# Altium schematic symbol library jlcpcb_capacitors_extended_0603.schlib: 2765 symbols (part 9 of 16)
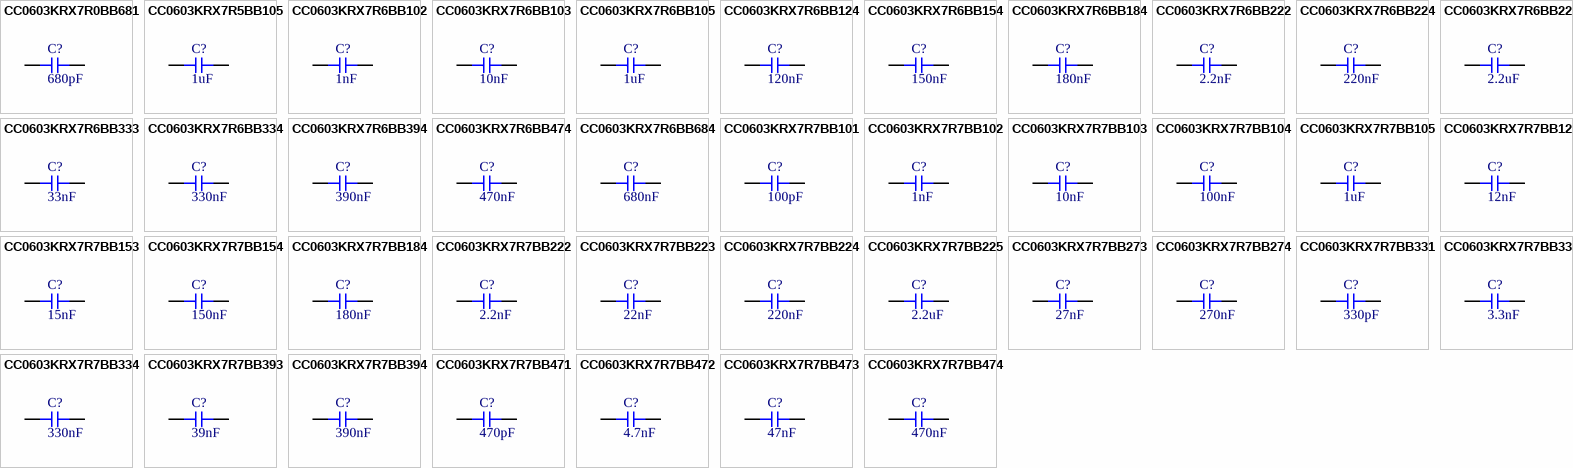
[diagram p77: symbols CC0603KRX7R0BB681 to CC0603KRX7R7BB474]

## CC0603KRX7R7BB334
designator C?  Capacitance: 330nF  (hidden comment: *)
Capacitor, Ceramic (MLCC), 330nF, ±10%, 16V, X7R, ±10%, SMD 0603; Manufacturer: YAGEO; Manufacturer Part Number: CC0603KRX7R7BB334
footprint CAP-0603 (0603 (1608M) Capacitor)
pins: 1, 2

## CC0603KRX7R7BB393
designator C?  Capacitance: 39nF  (hidden comment: *)
Capacitor, Ceramic (MLCC), 39nF, ±10%, 16V, X7R, ±10%, SMD 0603; Manufacturer: YAGEO; Manufacturer Part Number: CC0603KRX7R7BB393
footprint CAP-0603 (0603 (1608M) Capacitor)
pins: 1, 2

## CC0603KRX7R7BB394
designator C?  Capacitance: 390nF  (hidden comment: *)
Capacitor, Ceramic (MLCC), 390nF, ±10%, 16V, X7R, ±10%, SMD 0603; Manufacturer: YAGEO; Manufacturer Part Number: CC0603KRX7R7BB394
footprint CAP-0603 (0603 (1608M) Capacitor)
pins: 1, 2

## CC0603KRX7R7BB471
designator C?  Capacitance: 470pF  (hidden comment: *)
Capacitor, Ceramic (MLCC), 470pF, ±10%, 16V, X7R, ±10%, SMD 0603; Manufacturer: YAGEO; Manufacturer Part Number: CC0603KRX7R7BB471
footprint CAP-0603 (0603 (1608M) Capacitor)
pins: 1, 2

## CC0603KRX7R7BB472
designator C?  Capacitance: 4.7nF  (hidden comment: *)
Capacitor, Ceramic (MLCC), 4.7nF, ±10%, 16V, X7R, ±10%, SMD 0603; Manufacturer: YAGEO; Manufacturer Part Number: CC0603KRX7R7BB472
footprint CAP-0603 (0603 (1608M) Capacitor)
pins: 1, 2

## CC0603KRX7R7BB473
designator C?  Capacitance: 47nF  (hidden comment: *)
Capacitor, Ceramic (MLCC), 47nF, ±10%, 16V, X7R, ±10%, SMD 0603; Manufacturer: YAGEO; Manufacturer Part Number: CC0603KRX7R7BB473
footprint CAP-0603 (0603 (1608M) Capacitor)
pins: 1, 2

## CC0603KRX7R7BB474
designator C?  Capacitance: 470nF  (hidden comment: *)
Capacitor, Ceramic (MLCC), 470nF, ±10%, 16V, X7R, ±10%, SMD 0603; Manufacturer: YAGEO; Manufacturer Part Number: CC0603KRX7R7BB474
footprint CAP-0603 (0603 (1608M) Capacitor)
pins: 1, 2

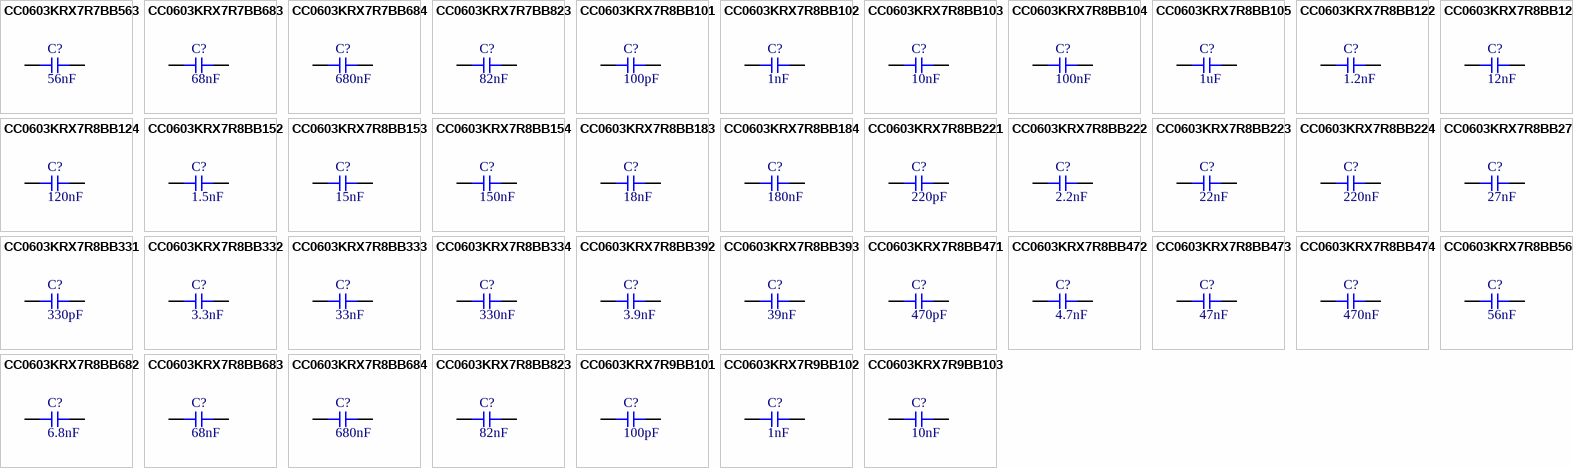
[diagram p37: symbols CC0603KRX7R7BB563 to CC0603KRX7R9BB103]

## CC0603KRX7R7BB563
designator C?  Capacitance: 56nF  (hidden comment: *)
Capacitor, Ceramic (MLCC), 56nF, ±10%, 16V, X7R, ±10%, SMD 0603; Manufacturer: YAGEO; Manufacturer Part Number: CC0603KRX7R7BB563
footprint CAP-0603 (0603 (1608M) Capacitor)
pins: 1, 2

## CC0603KRX7R7BB683
designator C?  Capacitance: 68nF  (hidden comment: *)
Capacitor, Ceramic (MLCC), 68nF, ±10%, 16V, X7R, ±10%, SMD 0603; Manufacturer: YAGEO; Manufacturer Part Number: CC0603KRX7R7BB683
footprint CAP-0603 (0603 (1608M) Capacitor)
pins: 1, 2

## CC0603KRX7R7BB684
designator C?  Capacitance: 680nF  (hidden comment: *)
Capacitor, Ceramic (MLCC), 680nF, ±10%, 16V, X7R, ±10%, SMD 0603; Manufacturer: YAGEO; Manufacturer Part Number: CC0603KRX7R7BB684
footprint CAP-0603 (0603 (1608M) Capacitor)
pins: 1, 2

## CC0603KRX7R7BB823
designator C?  Capacitance: 82nF  (hidden comment: *)
Capacitor, Ceramic (MLCC), 82nF, ±10%, 16V, X7R, ±10%, SMD 0603; Manufacturer: YAGEO; Manufacturer Part Number: CC0603KRX7R7BB823
footprint CAP-0603 (0603 (1608M) Capacitor)
pins: 1, 2

## CC0603KRX7R8BB101
designator C?  Capacitance: 100pF  (hidden comment: *)
Capacitor, Ceramic (MLCC), 100pF, ±10%, 25V, X7R, ±10%, SMD 0603; Manufacturer: YAGEO; Manufacturer Part Number: CC0603KRX7R8BB101
footprint CAP-0603 (0603 (1608M) Capacitor)
pins: 1, 2

## CC0603KRX7R8BB102
designator C?  Capacitance: 1nF  (hidden comment: *)
Capacitor, Ceramic (MLCC), 1nF, ±10%, 25V, X7R, ±10%, SMD 0603; Manufacturer: YAGEO; Manufacturer Part Number: CC0603KRX7R8BB102
footprint CAP-0603 (0603 (1608M) Capacitor)
pins: 1, 2

## CC0603KRX7R8BB103
designator C?  Capacitance: 10nF  (hidden comment: *)
Capacitor, Ceramic (MLCC), 10nF, ±10%, 25V, X7R, ±10%, SMD 0603; Manufacturer: YAGEO; Manufacturer Part Number: CC0603KRX7R8BB103
footprint CAP-0603 (0603 (1608M) Capacitor)
pins: 1, 2

## CC0603KRX7R8BB104
designator C?  Capacitance: 100nF  (hidden comment: *)
Capacitor, Ceramic (MLCC), 100nF, ±10%, 25V, X7R, ±10%, SMD 0603; Manufacturer: YAGEO; Manufacturer Part Number: CC0603KRX7R8BB104
footprint CAP-0603 (0603 (1608M) Capacitor)
pins: 1, 2

## CC0603KRX7R8BB105
designator C?  Capacitance: 1uF  (hidden comment: *)
Capacitor, Ceramic (MLCC), 1uF, ±10%, 25V, X7R, ±10%, SMD 0603; Manufacturer: YAGEO; Manufacturer Part Number: CC0603KRX7R8BB105
footprint CAP-0603 (0603 (1608M) Capacitor)
pins: 1, 2

## CC0603KRX7R8BB122
designator C?  Capacitance: 1.2nF  (hidden comment: *)
Capacitor, Ceramic (MLCC), 1.2nF, ±10%, 25V, X7R, ±10%, SMD 0603; Manufacturer: YAGEO; Manufacturer Part Number: CC0603KRX7R8BB122
footprint CAP-0603 (0603 (1608M) Capacitor)
pins: 1, 2

## CC0603KRX7R8BB123
designator C?  Capacitance: 12nF  (hidden comment: *)
Capacitor, Ceramic (MLCC), 12nF, ±10%, 25V, X7R, ±10%, SMD 0603; Manufacturer: YAGEO; Manufacturer Part Number: CC0603KRX7R8BB123
footprint CAP-0603 (0603 (1608M) Capacitor)
pins: 1, 2

## CC0603KRX7R8BB124
designator C?  Capacitance: 120nF  (hidden comment: *)
Capacitor, Ceramic (MLCC), 120nF, ±10%, 25V, X7R, ±10%, SMD 0603; Manufacturer: YAGEO; Manufacturer Part Number: CC0603KRX7R8BB124
footprint CAP-0603 (0603 (1608M) Capacitor)
pins: 1, 2

## CC0603KRX7R8BB152
designator C?  Capacitance: 1.5nF  (hidden comment: *)
Capacitor, Ceramic (MLCC), 1.5nF, ±10%, 25V, X7R, ±10%, SMD 0603; Manufacturer: YAGEO; Manufacturer Part Number: CC0603KRX7R8BB152
footprint CAP-0603 (0603 (1608M) Capacitor)
pins: 1, 2

## CC0603KRX7R8BB153
designator C?  Capacitance: 15nF  (hidden comment: *)
Capacitor, Ceramic (MLCC), 15nF, ±10%, 25V, X7R, ±10%, SMD 0603; Manufacturer: YAGEO; Manufacturer Part Number: CC0603KRX7R8BB153
footprint CAP-0603 (0603 (1608M) Capacitor)
pins: 1, 2

## CC0603KRX7R8BB154
designator C?  Capacitance: 150nF  (hidden comment: *)
Capacitor, Ceramic (MLCC), 150nF, ±10%, 25V, X7R, ±10%, SMD 0603; Manufacturer: YAGEO; Manufacturer Part Number: CC0603KRX7R8BB154
footprint CAP-0603 (0603 (1608M) Capacitor)
pins: 1, 2

## CC0603KRX7R8BB183
designator C?  Capacitance: 18nF  (hidden comment: *)
Capacitor, Ceramic (MLCC), 18nF, ±10%, 25V, X7R, ±10%, SMD 0603; Manufacturer: YAGEO; Manufacturer Part Number: CC0603KRX7R8BB183
footprint CAP-0603 (0603 (1608M) Capacitor)
pins: 1, 2

## CC0603KRX7R8BB184
designator C?  Capacitance: 180nF  (hidden comment: *)
Capacitor, Ceramic (MLCC), 180nF, ±10%, 25V, X7R, ±10%, SMD 0603; Manufacturer: YAGEO; Manufacturer Part Number: CC0603KRX7R8BB184
footprint CAP-0603 (0603 (1608M) Capacitor)
pins: 1, 2

## CC0603KRX7R8BB221
designator C?  Capacitance: 220pF  (hidden comment: *)
Capacitor, Ceramic (MLCC), 220pF, ±10%, 25V, X7R, ±10%, SMD 0603; Manufacturer: YAGEO; Manufacturer Part Number: CC0603KRX7R8BB221
footprint CAP-0603 (0603 (1608M) Capacitor)
pins: 1, 2

## CC0603KRX7R8BB222
designator C?  Capacitance: 2.2nF  (hidden comment: *)
Capacitor, Ceramic (MLCC), 2.2nF, ±10%, 25V, X7R, ±10%, SMD 0603; Manufacturer: YAGEO; Manufacturer Part Number: CC0603KRX7R8BB222
footprint CAP-0603 (0603 (1608M) Capacitor)
pins: 1, 2

## CC0603KRX7R8BB223
designator C?  Capacitance: 22nF  (hidden comment: *)
Capacitor, Ceramic (MLCC), 22nF, ±10%, 25V, X7R, ±10%, SMD 0603; Manufacturer: YAGEO; Manufacturer Part Number: CC0603KRX7R8BB223
footprint CAP-0603 (0603 (1608M) Capacitor)
pins: 1, 2

## CC0603KRX7R8BB224
designator C?  Capacitance: 220nF  (hidden comment: *)
Capacitor, Ceramic (MLCC), 220nF, ±10%, 25V, X7R, ±10%, SMD 0603; Manufacturer: YAGEO; Manufacturer Part Number: CC0603KRX7R8BB224
footprint CAP-0603 (0603 (1608M) Capacitor)
pins: 1, 2

## CC0603KRX7R8BB273
designator C?  Capacitance: 27nF  (hidden comment: *)
Capacitor, Ceramic (MLCC), 27nF, ±10%, 25V, X7R, ±10%, SMD 0603; Manufacturer: YAGEO; Manufacturer Part Number: CC0603KRX7R8BB273
footprint CAP-0603 (0603 (1608M) Capacitor)
pins: 1, 2

## CC0603KRX7R8BB331
designator C?  Capacitance: 330pF  (hidden comment: *)
Capacitor, Ceramic (MLCC), 330pF, ±10%, 25V, X7R, ±10%, SMD 0603; Manufacturer: YAGEO; Manufacturer Part Number: CC0603KRX7R8BB331
footprint CAP-0603 (0603 (1608M) Capacitor)
pins: 1, 2

## CC0603KRX7R8BB332
designator C?  Capacitance: 3.3nF  (hidden comment: *)
Capacitor, Ceramic (MLCC), 3.3nF, ±10%, 25V, X7R, ±10%, SMD 0603; Manufacturer: YAGEO; Manufacturer Part Number: CC0603KRX7R8BB332
footprint CAP-0603 (0603 (1608M) Capacitor)
pins: 1, 2

## CC0603KRX7R8BB333
designator C?  Capacitance: 33nF  (hidden comment: *)
Capacitor, Ceramic (MLCC), 33nF, ±10%, 25V, X7R, ±10%, SMD 0603; Manufacturer: YAGEO; Manufacturer Part Number: CC0603KRX7R8BB333
footprint CAP-0603 (0603 (1608M) Capacitor)
pins: 1, 2

## CC0603KRX7R8BB334
designator C?  Capacitance: 330nF  (hidden comment: *)
Capacitor, Ceramic (MLCC), 330nF, ±10%, 25V, X7R, ±10%, SMD 0603; Manufacturer: YAGEO; Manufacturer Part Number: CC0603KRX7R8BB334
footprint CAP-0603 (0603 (1608M) Capacitor)
pins: 1, 2

## CC0603KRX7R8BB392
designator C?  Capacitance: 3.9nF  (hidden comment: *)
Capacitor, Ceramic (MLCC), 3.9nF, ±10%, 25V, X7R, ±10%, SMD 0603; Manufacturer: YAGEO; Manufacturer Part Number: CC0603KRX7R8BB392
footprint CAP-0603 (0603 (1608M) Capacitor)
pins: 1, 2

## CC0603KRX7R8BB393
designator C?  Capacitance: 39nF  (hidden comment: *)
Capacitor, Ceramic (MLCC), 39nF, ±10%, 25V, X7R, ±10%, SMD 0603; Manufacturer: YAGEO; Manufacturer Part Number: CC0603KRX7R8BB393
footprint CAP-0603 (0603 (1608M) Capacitor)
pins: 1, 2

## CC0603KRX7R8BB471
designator C?  Capacitance: 470pF  (hidden comment: *)
Capacitor, Ceramic (MLCC), 470pF, ±10%, 25V, X7R, ±10%, SMD 0603; Manufacturer: YAGEO; Manufacturer Part Number: CC0603KRX7R8BB471
footprint CAP-0603 (0603 (1608M) Capacitor)
pins: 1, 2

## CC0603KRX7R8BB472
designator C?  Capacitance: 4.7nF  (hidden comment: *)
Capacitor, Ceramic (MLCC), 4.7nF, ±10%, 25V, X7R, ±10%, SMD 0603; Manufacturer: YAGEO; Manufacturer Part Number: CC0603KRX7R8BB472
footprint CAP-0603 (0603 (1608M) Capacitor)
pins: 1, 2

## CC0603KRX7R8BB473
designator C?  Capacitance: 47nF  (hidden comment: *)
Capacitor, Ceramic (MLCC), 47nF, ±10%, 25V, X7R, ±10%, SMD 0603; Manufacturer: YAGEO; Manufacturer Part Number: CC0603KRX7R8BB473
footprint CAP-0603 (0603 (1608M) Capacitor)
pins: 1, 2

## CC0603KRX7R8BB474
designator C?  Capacitance: 470nF  (hidden comment: *)
Capacitor, Ceramic (MLCC), 470nF, ±10%, 25V, X7R, ±10%, SMD 0603; Manufacturer: YAGEO; Manufacturer Part Number: CC0603KRX7R8BB474
footprint CAP-0603 (0603 (1608M) Capacitor)
pins: 1, 2

## CC0603KRX7R8BB563
designator C?  Capacitance: 56nF  (hidden comment: *)
Capacitor, Ceramic (MLCC), 56nF, ±10%, 25V, X7R, ±10%, SMD 0603; Manufacturer: YAGEO; Manufacturer Part Number: CC0603KRX7R8BB563
footprint CAP-0603 (0603 (1608M) Capacitor)
pins: 1, 2

## CC0603KRX7R8BB682
designator C?  Capacitance: 6.8nF  (hidden comment: *)
Capacitor, Ceramic (MLCC), 6.8nF, ±10%, 25V, X7R, ±10%, SMD 0603; Manufacturer: YAGEO; Manufacturer Part Number: CC0603KRX7R8BB682
footprint CAP-0603 (0603 (1608M) Capacitor)
pins: 1, 2

## CC0603KRX7R8BB683
designator C?  Capacitance: 68nF  (hidden comment: *)
Capacitor, Ceramic (MLCC), 68nF, ±10%, 25V, X7R, ±10%, SMD 0603; Manufacturer: YAGEO; Manufacturer Part Number: CC0603KRX7R8BB683
footprint CAP-0603 (0603 (1608M) Capacitor)
pins: 1, 2

## CC0603KRX7R8BB684
designator C?  Capacitance: 680nF  (hidden comment: *)
Capacitor, Ceramic (MLCC), 680nF, ±10%, 25V, X7R, ±10%, SMD 0603; Manufacturer: YAGEO; Manufacturer Part Number: CC0603KRX7R8BB684
footprint CAP-0603 (0603 (1608M) Capacitor)
pins: 1, 2

## CC0603KRX7R8BB823
designator C?  Capacitance: 82nF  (hidden comment: *)
Capacitor, Ceramic (MLCC), 82nF, ±10%, 25V, X7R, ±10%, SMD 0603; Manufacturer: YAGEO; Manufacturer Part Number: CC0603KRX7R8BB823
footprint CAP-0603 (0603 (1608M) Capacitor)
pins: 1, 2

## CC0603KRX7R9BB101
designator C?  Capacitance: 100pF  (hidden comment: *)
Capacitor, Ceramic (MLCC), 100pF, ±10%, 50V, X7R, ±10%, SMD 0603; Manufacturer: YAGEO; Manufacturer Part Number: CC0603KRX7R9BB101
footprint CAP-0603 (0603 (1608M) Capacitor)
pins: 1, 2

## CC0603KRX7R9BB102
designator C?  Capacitance: 1nF  (hidden comment: *)
Capacitor, Ceramic (MLCC), 1nF, ±10%, 50V, X7R, ±10%, SMD 0603; Manufacturer: YAGEO; Manufacturer Part Number: CC0603KRX7R9BB102
footprint CAP-0603 (0603 (1608M) Capacitor)
pins: 1, 2

## CC0603KRX7R9BB103
designator C?  Capacitance: 10nF  (hidden comment: *)
Capacitor, Ceramic (MLCC), 10nF, ±10%, 50V, X7R, ±10%, SMD 0603; Manufacturer: YAGEO; Manufacturer Part Number: CC0603KRX7R9BB103
footprint CAP-0603 (0603 (1608M) Capacitor)
pins: 1, 2

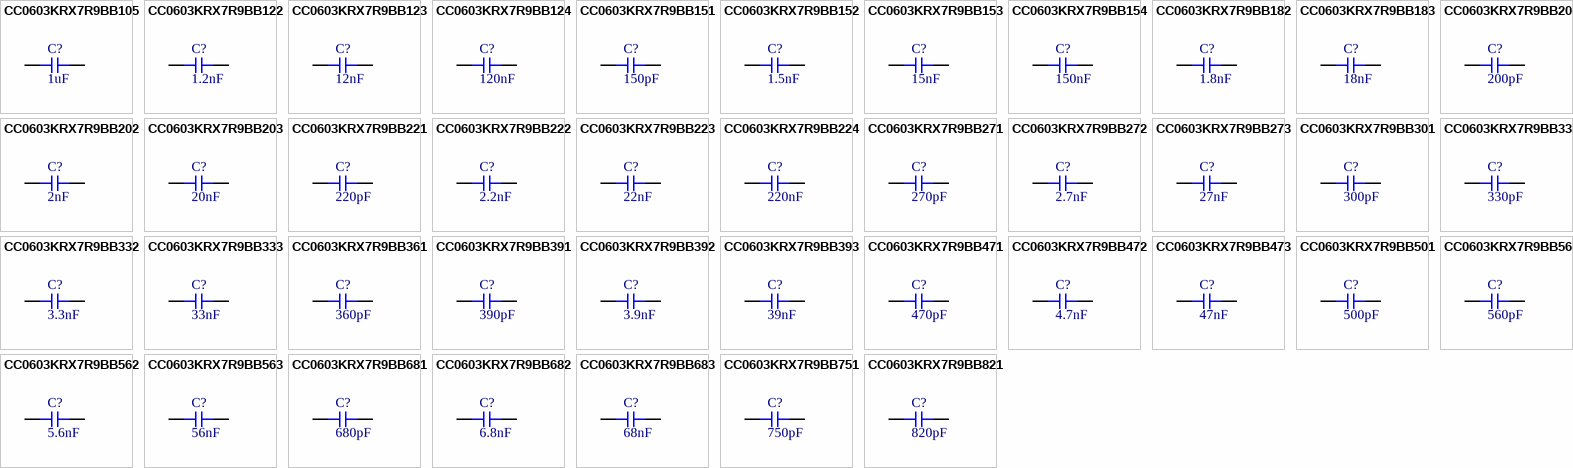
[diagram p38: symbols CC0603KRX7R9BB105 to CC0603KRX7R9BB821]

## CC0603KRX7R9BB105
designator C?  Capacitance: 1uF  (hidden comment: *)
Capacitor, Ceramic (MLCC), 1uF, ±10%, 50V, X7R, ±10%, SMD 0603; Manufacturer: YAGEO; Manufacturer Part Number: CC0603KRX7R9BB105
footprint CAP-0603 (0603 (1608M) Capacitor)
pins: 1, 2

## CC0603KRX7R9BB122
designator C?  Capacitance: 1.2nF  (hidden comment: *)
Capacitor, Ceramic (MLCC), 1.2nF, ±10%, 50V, X7R, ±10%, SMD 0603; Manufacturer: YAGEO; Manufacturer Part Number: CC0603KRX7R9BB122
footprint CAP-0603 (0603 (1608M) Capacitor)
pins: 1, 2

## CC0603KRX7R9BB123
designator C?  Capacitance: 12nF  (hidden comment: *)
Capacitor, Ceramic (MLCC), 12nF, ±10%, 50V, X7R, ±10%, SMD 0603; Manufacturer: YAGEO; Manufacturer Part Number: CC0603KRX7R9BB123
footprint CAP-0603 (0603 (1608M) Capacitor)
pins: 1, 2

## CC0603KRX7R9BB124
designator C?  Capacitance: 120nF  (hidden comment: *)
Capacitor, Ceramic (MLCC), 120nF, ±10%, 50V, X7R, ±10%, SMD 0603; Manufacturer: YAGEO; Manufacturer Part Number: CC0603KRX7R9BB124
footprint CAP-0603 (0603 (1608M) Capacitor)
pins: 1, 2

## CC0603KRX7R9BB151
designator C?  Capacitance: 150pF  (hidden comment: *)
Capacitor, Ceramic (MLCC), 150pF, ±10%, 50V, X7R, ±10%, SMD 0603; Manufacturer: YAGEO; Manufacturer Part Number: CC0603KRX7R9BB151
footprint CAP-0603 (0603 (1608M) Capacitor)
pins: 1, 2

## CC0603KRX7R9BB152
designator C?  Capacitance: 1.5nF  (hidden comment: *)
Capacitor, Ceramic (MLCC), 1.5nF, ±10%, 50V, X7R, ±10%, SMD 0603; Manufacturer: YAGEO; Manufacturer Part Number: CC0603KRX7R9BB152
footprint CAP-0603 (0603 (1608M) Capacitor)
pins: 1, 2

## CC0603KRX7R9BB153
designator C?  Capacitance: 15nF  (hidden comment: *)
Capacitor, Ceramic (MLCC), 15nF, ±10%, 50V, X7R, ±10%, SMD 0603; Manufacturer: YAGEO; Manufacturer Part Number: CC0603KRX7R9BB153
footprint CAP-0603 (0603 (1608M) Capacitor)
pins: 1, 2

## CC0603KRX7R9BB154
designator C?  Capacitance: 150nF  (hidden comment: *)
Capacitor, Ceramic (MLCC), 150nF, ±10%, 50V, X7R, ±10%, SMD 0603; Manufacturer: YAGEO; Manufacturer Part Number: CC0603KRX7R9BB154
footprint CAP-0603 (0603 (1608M) Capacitor)
pins: 1, 2

## CC0603KRX7R9BB182
designator C?  Capacitance: 1.8nF  (hidden comment: *)
Capacitor, Ceramic (MLCC), 1.8nF, ±10%, 50V, X7R, ±10%, SMD 0603; Manufacturer: YAGEO; Manufacturer Part Number: CC0603KRX7R9BB182
footprint CAP-0603 (0603 (1608M) Capacitor)
pins: 1, 2

## CC0603KRX7R9BB183
designator C?  Capacitance: 18nF  (hidden comment: *)
Capacitor, Ceramic (MLCC), 18nF, ±10%, 50V, X7R, ±10%, SMD 0603; Manufacturer: YAGEO; Manufacturer Part Number: CC0603KRX7R9BB183
footprint CAP-0603 (0603 (1608M) Capacitor)
pins: 1, 2

## CC0603KRX7R9BB201
designator C?  Capacitance: 200pF  (hidden comment: *)
Capacitor, Ceramic (MLCC), 200pF, ±10%, 50V, X7R, ±10%, SMD 0603; Manufacturer: YAGEO; Manufacturer Part Number: CC0603KRX7R9BB201
footprint CAP-0603 (0603 (1608M) Capacitor)
pins: 1, 2

## CC0603KRX7R9BB202
designator C?  Capacitance: 2nF  (hidden comment: *)
Capacitor, Ceramic (MLCC), 2nF, ±10%, 50V, X7R, ±10%, SMD 0603; Manufacturer: YAGEO; Manufacturer Part Number: CC0603KRX7R9BB202
footprint CAP-0603 (0603 (1608M) Capacitor)
pins: 1, 2

## CC0603KRX7R9BB203
designator C?  Capacitance: 20nF  (hidden comment: *)
Capacitor, Ceramic (MLCC), 20nF, ±10%, 50V, X7R, ±10%, SMD 0603; Manufacturer: YAGEO; Manufacturer Part Number: CC0603KRX7R9BB203
footprint CAP-0603 (0603 (1608M) Capacitor)
pins: 1, 2

## CC0603KRX7R9BB221
designator C?  Capacitance: 220pF  (hidden comment: *)
Capacitor, Ceramic (MLCC), 220pF, ±10%, 50V, X7R, ±10%, SMD 0603; Manufacturer: YAGEO; Manufacturer Part Number: CC0603KRX7R9BB221
footprint CAP-0603 (0603 (1608M) Capacitor)
pins: 1, 2

## CC0603KRX7R9BB222
designator C?  Capacitance: 2.2nF  (hidden comment: *)
Capacitor, Ceramic (MLCC), 2.2nF, ±10%, 50V, X7R, ±10%, SMD 0603; Manufacturer: YAGEO; Manufacturer Part Number: CC0603KRX7R9BB222
footprint CAP-0603 (0603 (1608M) Capacitor)
pins: 1, 2

## CC0603KRX7R9BB223
designator C?  Capacitance: 22nF  (hidden comment: *)
Capacitor, Ceramic (MLCC), 22nF, ±10%, 50V, X7R, ±10%, SMD 0603; Manufacturer: YAGEO; Manufacturer Part Number: CC0603KRX7R9BB223
footprint CAP-0603 (0603 (1608M) Capacitor)
pins: 1, 2

## CC0603KRX7R9BB224
designator C?  Capacitance: 220nF  (hidden comment: *)
Capacitor, Ceramic (MLCC), 220nF, ±10%, 50V, X7R, ±10%, SMD 0603; Manufacturer: YAGEO; Manufacturer Part Number: CC0603KRX7R9BB224
footprint CAP-0603 (0603 (1608M) Capacitor)
pins: 1, 2

## CC0603KRX7R9BB271
designator C?  Capacitance: 270pF  (hidden comment: *)
Capacitor, Ceramic (MLCC), 270pF, ±10%, 50V, X7R, ±10%, SMD 0603; Manufacturer: YAGEO; Manufacturer Part Number: CC0603KRX7R9BB271
footprint CAP-0603 (0603 (1608M) Capacitor)
pins: 1, 2

## CC0603KRX7R9BB272
designator C?  Capacitance: 2.7nF  (hidden comment: *)
Capacitor, Ceramic (MLCC), 2.7nF, ±10%, 50V, X7R, ±10%, SMD 0603; Manufacturer: YAGEO; Manufacturer Part Number: CC0603KRX7R9BB272
footprint CAP-0603 (0603 (1608M) Capacitor)
pins: 1, 2

## CC0603KRX7R9BB273
designator C?  Capacitance: 27nF  (hidden comment: *)
Capacitor, Ceramic (MLCC), 27nF, ±10%, 50V, X7R, ±10%, SMD 0603; Manufacturer: YAGEO; Manufacturer Part Number: CC0603KRX7R9BB273
footprint CAP-0603 (0603 (1608M) Capacitor)
pins: 1, 2

## CC0603KRX7R9BB301
designator C?  Capacitance: 300pF  (hidden comment: *)
Capacitor, Ceramic (MLCC), 300pF, ±10%, 50V, X7R, ±10%, SMD 0603; Manufacturer: YAGEO; Manufacturer Part Number: CC0603KRX7R9BB301
footprint CAP-0603 (0603 (1608M) Capacitor)
pins: 1, 2

## CC0603KRX7R9BB331
designator C?  Capacitance: 330pF  (hidden comment: *)
Capacitor, Ceramic (MLCC), 330pF, ±10%, 50V, X7R, ±10%, SMD 0603; Manufacturer: YAGEO; Manufacturer Part Number: CC0603KRX7R9BB331
footprint CAP-0603 (0603 (1608M) Capacitor)
pins: 1, 2

## CC0603KRX7R9BB332
designator C?  Capacitance: 3.3nF  (hidden comment: *)
Capacitor, Ceramic (MLCC), 3.3nF, ±10%, 50V, X7R, ±10%, SMD 0603; Manufacturer: YAGEO; Manufacturer Part Number: CC0603KRX7R9BB332
footprint CAP-0603 (0603 (1608M) Capacitor)
pins: 1, 2

## CC0603KRX7R9BB333
designator C?  Capacitance: 33nF  (hidden comment: *)
Capacitor, Ceramic (MLCC), 33nF, ±10%, 50V, X7R, ±10%, SMD 0603; Manufacturer: YAGEO; Manufacturer Part Number: CC0603KRX7R9BB333
footprint CAP-0603 (0603 (1608M) Capacitor)
pins: 1, 2

## CC0603KRX7R9BB361
designator C?  Capacitance: 360pF  (hidden comment: *)
Capacitor, Ceramic (MLCC), 360pF, ±10%, 50V, X7R, ±10%, SMD 0603; Manufacturer: YAGEO; Manufacturer Part Number: CC0603KRX7R9BB361
footprint CAP-0603 (0603 (1608M) Capacitor)
pins: 1, 2

## CC0603KRX7R9BB391
designator C?  Capacitance: 390pF  (hidden comment: *)
Capacitor, Ceramic (MLCC), 390pF, ±10%, 50V, X7R, ±10%, SMD 0603; Manufacturer: YAGEO; Manufacturer Part Number: CC0603KRX7R9BB391
footprint CAP-0603 (0603 (1608M) Capacitor)
pins: 1, 2

## CC0603KRX7R9BB392
designator C?  Capacitance: 3.9nF  (hidden comment: *)
Capacitor, Ceramic (MLCC), 3.9nF, ±10%, 50V, X7R, ±10%, SMD 0603; Manufacturer: YAGEO; Manufacturer Part Number: CC0603KRX7R9BB392
footprint CAP-0603 (0603 (1608M) Capacitor)
pins: 1, 2

## CC0603KRX7R9BB393
designator C?  Capacitance: 39nF  (hidden comment: *)
Capacitor, Ceramic (MLCC), 39nF, ±10%, 50V, X7R, ±10%, SMD 0603; Manufacturer: YAGEO; Manufacturer Part Number: CC0603KRX7R9BB393
footprint CAP-0603 (0603 (1608M) Capacitor)
pins: 1, 2

## CC0603KRX7R9BB471
designator C?  Capacitance: 470pF  (hidden comment: *)
Capacitor, Ceramic (MLCC), 470pF, ±10%, 50V, X7R, ±10%, SMD 0603; Manufacturer: YAGEO; Manufacturer Part Number: CC0603KRX7R9BB471
footprint CAP-0603 (0603 (1608M) Capacitor)
pins: 1, 2

## CC0603KRX7R9BB472
designator C?  Capacitance: 4.7nF  (hidden comment: *)
Capacitor, Ceramic (MLCC), 4.7nF, ±10%, 50V, X7R, ±10%, SMD 0603; Manufacturer: YAGEO; Manufacturer Part Number: CC0603KRX7R9BB472
footprint CAP-0603 (0603 (1608M) Capacitor)
pins: 1, 2

## CC0603KRX7R9BB473
designator C?  Capacitance: 47nF  (hidden comment: *)
Capacitor, Ceramic (MLCC), 47nF, ±10%, 50V, X7R, ±10%, SMD 0603; Manufacturer: YAGEO; Manufacturer Part Number: CC0603KRX7R9BB473
footprint CAP-0603 (0603 (1608M) Capacitor)
pins: 1, 2

## CC0603KRX7R9BB501
designator C?  Capacitance: 500pF  (hidden comment: *)
Capacitor, Ceramic (MLCC), 500pF, ±10%, 50V, X7R, ±10%, SMD 0603; Manufacturer: YAGEO; Manufacturer Part Number: CC0603KRX7R9BB501
footprint CAP-0603 (0603 (1608M) Capacitor)
pins: 1, 2

## CC0603KRX7R9BB561
designator C?  Capacitance: 560pF  (hidden comment: *)
Capacitor, Ceramic (MLCC), 560pF, ±10%, 50V, X7R, ±10%, SMD 0603; Manufacturer: YAGEO; Manufacturer Part Number: CC0603KRX7R9BB561
footprint CAP-0603 (0603 (1608M) Capacitor)
pins: 1, 2

## CC0603KRX7R9BB562
designator C?  Capacitance: 5.6nF  (hidden comment: *)
Capacitor, Ceramic (MLCC), 5.6nF, ±10%, 50V, X7R, ±10%, SMD 0603; Manufacturer: YAGEO; Manufacturer Part Number: CC0603KRX7R9BB562
footprint CAP-0603 (0603 (1608M) Capacitor)
pins: 1, 2

## CC0603KRX7R9BB563
designator C?  Capacitance: 56nF  (hidden comment: *)
Capacitor, Ceramic (MLCC), 56nF, ±10%, 50V, X7R, ±10%, SMD 0603; Manufacturer: YAGEO; Manufacturer Part Number: CC0603KRX7R9BB563
footprint CAP-0603 (0603 (1608M) Capacitor)
pins: 1, 2

## CC0603KRX7R9BB681
designator C?  Capacitance: 680pF  (hidden comment: *)
Capacitor, Ceramic (MLCC), 680pF, ±10%, 50V, X7R, ±10%, SMD 0603; Manufacturer: YAGEO; Manufacturer Part Number: CC0603KRX7R9BB681
footprint CAP-0603 (0603 (1608M) Capacitor)
pins: 1, 2

## CC0603KRX7R9BB682
designator C?  Capacitance: 6.8nF  (hidden comment: *)
Capacitor, Ceramic (MLCC), 6.8nF, ±10%, 50V, X7R, ±10%, SMD 0603; Manufacturer: YAGEO; Manufacturer Part Number: CC0603KRX7R9BB682
footprint CAP-0603 (0603 (1608M) Capacitor)
pins: 1, 2

## CC0603KRX7R9BB683
designator C?  Capacitance: 68nF  (hidden comment: *)
Capacitor, Ceramic (MLCC), 68nF, ±10%, 50V, X7R, ±10%, SMD 0603; Manufacturer: YAGEO; Manufacturer Part Number: CC0603KRX7R9BB683
footprint CAP-0603 (0603 (1608M) Capacitor)
pins: 1, 2

## CC0603KRX7R9BB751
designator C?  Capacitance: 750pF  (hidden comment: *)
Capacitor, Ceramic (MLCC), 750pF, ±10%, 50V, X7R, ±10%, SMD 0603; Manufacturer: YAGEO; Manufacturer Part Number: CC0603KRX7R9BB751
footprint CAP-0603 (0603 (1608M) Capacitor)
pins: 1, 2

## CC0603KRX7R9BB821
designator C?  Capacitance: 820pF  (hidden comment: *)
Capacitor, Ceramic (MLCC), 820pF, ±10%, 50V, X7R, ±10%, SMD 0603; Manufacturer: YAGEO; Manufacturer Part Number: CC0603KRX7R9BB821
footprint CAP-0603 (0603 (1608M) Capacitor)
pins: 1, 2

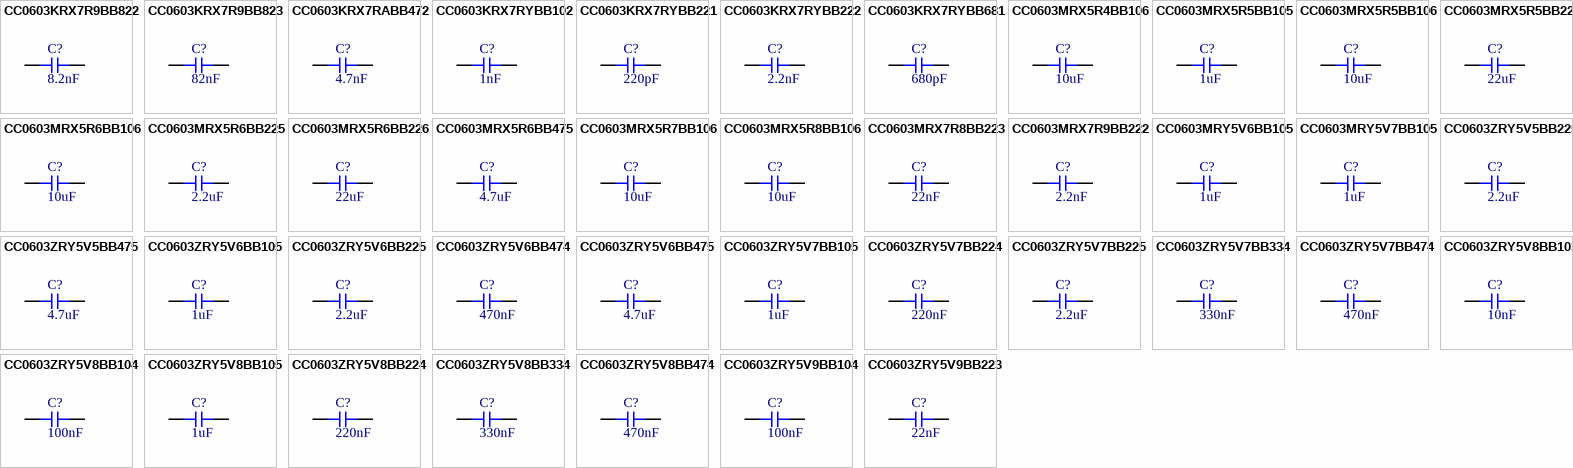
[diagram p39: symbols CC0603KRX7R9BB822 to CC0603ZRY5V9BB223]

## CC0603KRX7R9BB822
designator C?  Capacitance: 8.2nF  (hidden comment: *)
Capacitor, Ceramic (MLCC), 8.2nF, ±10%, 50V, X7R, ±10%, SMD 0603; Manufacturer: YAGEO; Manufacturer Part Number: CC0603KRX7R9BB822
footprint CAP-0603 (0603 (1608M) Capacitor)
pins: 1, 2

## CC0603KRX7R9BB823
designator C?  Capacitance: 82nF  (hidden comment: *)
Capacitor, Ceramic (MLCC), 82nF, ±10%, 50V, X7R, ±10%, SMD 0603; Manufacturer: YAGEO; Manufacturer Part Number: CC0603KRX7R9BB823
footprint CAP-0603 (0603 (1608M) Capacitor)
pins: 1, 2

## CC0603KRX7RABB472
designator C?  Capacitance: 4.7nF  (hidden comment: *)
Capacitor, Ceramic (MLCC), 4.7nF, ±10%, 200V, X7R, ±10%, SMD 0603; Manufacturer: YAGEO; Manufacturer Part Number: CC0603KRX7RABB472
footprint CAP-0603 (0603 (1608M) Capacitor)
pins: 1, 2

## CC0603KRX7RYBB102
designator C?  Capacitance: 1nF  (hidden comment: *)
Capacitor, Ceramic (MLCC), 1nF, ±10%, 250V, X7R, ±10%, SMD 0603; Manufacturer: YAGEO; Manufacturer Part Number: CC0603KRX7RYBB102
footprint CAP-0603 (0603 (1608M) Capacitor)
pins: 1, 2

## CC0603KRX7RYBB221
designator C?  Capacitance: 220pF  (hidden comment: *)
Capacitor, Ceramic (MLCC), 220pF, ±10%, 250V, X7R, ±10%, SMD 0603; Manufacturer: YAGEO; Manufacturer Part Number: CC0603KRX7RYBB221
footprint CAP-0603 (0603 (1608M) Capacitor)
pins: 1, 2

## CC0603KRX7RYBB222
designator C?  Capacitance: 2.2nF  (hidden comment: *)
Capacitor, Ceramic (MLCC), 2.2nF, ±10%, 250V, X7R, ±10%, SMD 0603; Manufacturer: YAGEO; Manufacturer Part Number: CC0603KRX7RYBB222
footprint CAP-0603 (0603 (1608M) Capacitor)
pins: 1, 2

## CC0603KRX7RYBB681
designator C?  Capacitance: 680pF  (hidden comment: *)
Capacitor, Ceramic (MLCC), 680pF, ±10%, 250V, X7R, ±10%, SMD 0603; Manufacturer: YAGEO; Manufacturer Part Number: CC0603KRX7RYBB681
footprint CAP-0603 (0603 (1608M) Capacitor)
pins: 1, 2

## CC0603MRX5R4BB106
designator C?  Capacitance: 10uF  (hidden comment: *)
Capacitor, Ceramic (MLCC), 10uF, ±20%, 4V, X5R, ±20%, SMD 0603; Manufacturer: YAGEO; Manufacturer Part Number: CC0603MRX5R4BB106
footprint CAP-0603 (0603 (1608M) Capacitor)
pins: 1, 2

## CC0603MRX5R5BB105
designator C?  Capacitance: 1uF  (hidden comment: *)
Capacitor, Ceramic (MLCC), 1uF, ±20%, 6.3V, X5R, ±20%, SMD 0603; Manufacturer: YAGEO; Manufacturer Part Number: CC0603MRX5R5BB105
footprint CAP-0603 (0603 (1608M) Capacitor)
pins: 1, 2

## CC0603MRX5R5BB106
designator C?  Capacitance: 10uF  (hidden comment: *)
Capacitor, Ceramic (MLCC), 10uF, ±20%, 6.3V, X5R, ±20%, SMD 0603; Manufacturer: YAGEO; Manufacturer Part Number: CC0603MRX5R5BB106
footprint CAP-0603 (0603 (1608M) Capacitor)
pins: 1, 2

## CC0603MRX5R5BB226
designator C?  Capacitance: 22uF  (hidden comment: *)
Capacitor, Ceramic (MLCC), 22uF, ±20%, 6.3V, X5R, ±20%, SMD 0603; Manufacturer: YAGEO; Manufacturer Part Number: CC0603MRX5R5BB226
footprint CAP-0603 (0603 (1608M) Capacitor)
pins: 1, 2

## CC0603MRX5R6BB106
designator C?  Capacitance: 10uF  (hidden comment: *)
Capacitor, Ceramic (MLCC), 10uF, ±20%, 10V, X5R, ±20%, SMD 0603; Manufacturer: YAGEO; Manufacturer Part Number: CC0603MRX5R6BB106
footprint CAP-0603 (0603 (1608M) Capacitor)
pins: 1, 2

## CC0603MRX5R6BB225
designator C?  Capacitance: 2.2uF  (hidden comment: *)
Capacitor, Ceramic (MLCC), 2.2uF, ±20%, 10V, X5R, ±20%, SMD 0603; Manufacturer: YAGEO; Manufacturer Part Number: CC0603MRX5R6BB225
footprint CAP-0603 (0603 (1608M) Capacitor)
pins: 1, 2

## CC0603MRX5R6BB226
designator C?  Capacitance: 22uF  (hidden comment: *)
Capacitor, Ceramic (MLCC), 22uF, ±20%, 10V, X5R, ±20%, SMD 0603; Manufacturer: YAGEO; Manufacturer Part Number: CC0603MRX5R6BB226
footprint CAP-0603 (0603 (1608M) Capacitor)
pins: 1, 2

## CC0603MRX5R6BB475
designator C?  Capacitance: 4.7uF  (hidden comment: *)
Capacitor, Ceramic (MLCC), 4.7uF, ±20%, 10V, X5R, ±20%, SMD 0603; Manufacturer: YAGEO; Manufacturer Part Number: CC0603MRX5R6BB475
footprint CAP-0603 (0603 (1608M) Capacitor)
pins: 1, 2

## CC0603MRX5R7BB106
designator C?  Capacitance: 10uF  (hidden comment: *)
Capacitor, Ceramic (MLCC), 10uF, ±20%, 16V, X5R, ±20%, SMD 0603; Manufacturer: YAGEO; Manufacturer Part Number: CC0603MRX5R7BB106
footprint CAP-0603 (0603 (1608M) Capacitor)
pins: 1, 2

## CC0603MRX5R8BB106
designator C?  Capacitance: 10uF  (hidden comment: *)
Capacitor, Ceramic (MLCC), 10uF, ±20%, 25V, X5R, ±20%, SMD 0603; Manufacturer: YAGEO; Manufacturer Part Number: CC0603MRX5R8BB106
footprint CAP-0603 (0603 (1608M) Capacitor)
pins: 1, 2

## CC0603MRX7R8BB223
designator C?  Capacitance: 22nF  (hidden comment: *)
Capacitor, Ceramic (MLCC), 22nF, ±20%, 25V, X7R, ±20%, SMD 0603; Manufacturer: YAGEO; Manufacturer Part Number: CC0603MRX7R8BB223
footprint CAP-0603 (0603 (1608M) Capacitor)
pins: 1, 2

## CC0603MRX7R9BB222
designator C?  Capacitance: 2.2nF  (hidden comment: *)
Capacitor, Ceramic (MLCC), 2.2nF, ±20%, 50V, X7R, ±20%, SMD 0603; Manufacturer: YAGEO; Manufacturer Part Number: CC0603MRX7R9BB222
footprint CAP-0603 (0603 (1608M) Capacitor)
pins: 1, 2

## CC0603MRY5V6BB105
designator C?  Capacitance: 1uF  (hidden comment: *)
Capacitor, Ceramic (MLCC), 1uF, ±20%, 10V, Y5V, ±20%, SMD 0603; Manufacturer: YAGEO; Manufacturer Part Number: CC0603MRY5V6BB105
footprint CAP-0603 (0603 (1608M) Capacitor)
pins: 1, 2

## CC0603MRY5V7BB105
designator C?  Capacitance: 1uF  (hidden comment: *)
Capacitor, Ceramic (MLCC), 1uF, ±20%, 16V, Y5V, ±20%, SMD 0603; Manufacturer: YAGEO; Manufacturer Part Number: CC0603MRY5V7BB105
footprint CAP-0603 (0603 (1608M) Capacitor)
pins: 1, 2

## CC0603ZRY5V5BB225
designator C?  Capacitance: 2.2uF  (hidden comment: *)
Capacitor, Ceramic (MLCC), 2.2uF, 6.3V, Y5V, SMD 0603; Manufacturer: YAGEO; Manufacturer Part Number: CC0603ZRY5V5BB225; Temperature Rating: -20%~+80%
footprint CAP-0603 (0603 (1608M) Capacitor)
pins: 1, 2

## CC0603ZRY5V5BB475
designator C?  Capacitance: 4.7uF  (hidden comment: *)
Capacitor, Ceramic (MLCC), 4.7uF, 6.3V, Y5V, SMD 0603; Manufacturer: YAGEO; Manufacturer Part Number: CC0603ZRY5V5BB475; Temperature Rating: -20%~+80%
footprint CAP-0603 (0603 (1608M) Capacitor)
pins: 1, 2

## CC0603ZRY5V6BB105
designator C?  Capacitance: 1uF  (hidden comment: *)
Capacitor, Ceramic (MLCC), 1uF, 10V, Y5V, SMD 0603; Manufacturer: YAGEO; Manufacturer Part Number: CC0603ZRY5V6BB105; Temperature Rating: -20%~+80%
footprint CAP-0603 (0603 (1608M) Capacitor)
pins: 1, 2

## CC0603ZRY5V6BB225
designator C?  Capacitance: 2.2uF  (hidden comment: *)
Capacitor, Ceramic (MLCC), 2.2uF, 10V, Y5V, SMD 0603; Manufacturer: YAGEO; Manufacturer Part Number: CC0603ZRY5V6BB225; Temperature Rating: -20%~+80%
footprint CAP-0603 (0603 (1608M) Capacitor)
pins: 1, 2

## CC0603ZRY5V6BB474
designator C?  Capacitance: 470nF  (hidden comment: *)
Capacitor, Ceramic (MLCC), 470nF, 10V, Y5V, SMD 0603; Manufacturer: YAGEO; Manufacturer Part Number: CC0603ZRY5V6BB474; Temperature Rating: -20%~+80%
footprint CAP-0603 (0603 (1608M) Capacitor)
pins: 1, 2

## CC0603ZRY5V6BB475
designator C?  Capacitance: 4.7uF  (hidden comment: *)
Capacitor, Ceramic (MLCC), 4.7uF, 10V, Y5V, SMD 0603; Manufacturer: YAGEO; Manufacturer Part Number: CC0603ZRY5V6BB475; Temperature Rating: -20%~+80%
footprint CAP-0603 (0603 (1608M) Capacitor)
pins: 1, 2

## CC0603ZRY5V7BB105
designator C?  Capacitance: 1uF  (hidden comment: *)
Capacitor, Ceramic (MLCC), 1uF, 16V, Y5V, SMD 0603; Manufacturer: YAGEO; Manufacturer Part Number: CC0603ZRY5V7BB105; Temperature Rating: -20%~+80%
footprint CAP-0603 (0603 (1608M) Capacitor)
pins: 1, 2

## CC0603ZRY5V7BB224
designator C?  Capacitance: 220nF  (hidden comment: *)
Capacitor, Ceramic (MLCC), 220nF, 16V, Y5V, SMD 0603; Manufacturer: YAGEO; Manufacturer Part Number: CC0603ZRY5V7BB224; Temperature Rating: -20%~+80%
footprint CAP-0603 (0603 (1608M) Capacitor)
pins: 1, 2

## CC0603ZRY5V7BB225
designator C?  Capacitance: 2.2uF  (hidden comment: *)
Capacitor, Ceramic (MLCC), 2.2uF, 16V, Y5V, SMD 0603; Manufacturer: YAGEO; Manufacturer Part Number: CC0603ZRY5V7BB225; Temperature Rating: -20%~+80%
footprint CAP-0603 (0603 (1608M) Capacitor)
pins: 1, 2

## CC0603ZRY5V7BB334
designator C?  Capacitance: 330nF  (hidden comment: *)
Capacitor, Ceramic (MLCC), 330nF, 16V, Y5V, SMD 0603; Manufacturer: YAGEO; Manufacturer Part Number: CC0603ZRY5V7BB334; Temperature Rating: -20%~+80%
footprint CAP-0603 (0603 (1608M) Capacitor)
pins: 1, 2

## CC0603ZRY5V7BB474
designator C?  Capacitance: 470nF  (hidden comment: *)
Capacitor, Ceramic (MLCC), 470nF, 16V, Y5V, SMD 0603; Manufacturer: YAGEO; Manufacturer Part Number: CC0603ZRY5V7BB474; Temperature Rating: -20%~+80%
footprint CAP-0603 (0603 (1608M) Capacitor)
pins: 1, 2

## CC0603ZRY5V8BB103
designator C?  Capacitance: 10nF  (hidden comment: *)
Capacitor, Ceramic (MLCC), 10nF, 25V, Y5V, SMD 0603; Manufacturer: YAGEO; Manufacturer Part Number: CC0603ZRY5V8BB103; Temperature Rating: -20%~+80%
footprint CAP-0603 (0603 (1608M) Capacitor)
pins: 1, 2

## CC0603ZRY5V8BB104
designator C?  Capacitance: 100nF  (hidden comment: *)
Capacitor, Ceramic (MLCC), 100nF, 25V, Y5V, SMD 0603; Manufacturer: YAGEO; Manufacturer Part Number: CC0603ZRY5V8BB104; Temperature Rating: -20%~+80%
footprint CAP-0603 (0603 (1608M) Capacitor)
pins: 1, 2

## CC0603ZRY5V8BB105
designator C?  Capacitance: 1uF  (hidden comment: *)
Capacitor, Ceramic (MLCC), 1uF, 25V, Y5V, SMD 0603; Manufacturer: YAGEO; Manufacturer Part Number: CC0603ZRY5V8BB105; Temperature Rating: -20%~+80%
footprint CAP-0603 (0603 (1608M) Capacitor)
pins: 1, 2

## CC0603ZRY5V8BB224
designator C?  Capacitance: 220nF  (hidden comment: *)
Capacitor, Ceramic (MLCC), 220nF, 25V, Y5V, SMD 0603; Manufacturer: YAGEO; Manufacturer Part Number: CC0603ZRY5V8BB224; Temperature Rating: -20%~+80%
footprint CAP-0603 (0603 (1608M) Capacitor)
pins: 1, 2

## CC0603ZRY5V8BB334
designator C?  Capacitance: 330nF  (hidden comment: *)
Capacitor, Ceramic (MLCC), 330nF, 25V, Y5V, SMD 0603; Manufacturer: YAGEO; Manufacturer Part Number: CC0603ZRY5V8BB334; Temperature Rating: -20%~+80%
footprint CAP-0603 (0603 (1608M) Capacitor)
pins: 1, 2

## CC0603ZRY5V8BB474
designator C?  Capacitance: 470nF  (hidden comment: *)
Capacitor, Ceramic (MLCC), 470nF, 25V, Y5V, SMD 0603; Manufacturer: YAGEO; Manufacturer Part Number: CC0603ZRY5V8BB474; Temperature Rating: -20%~+80%
footprint CAP-0603 (0603 (1608M) Capacitor)
pins: 1, 2

## CC0603ZRY5V9BB104
designator C?  Capacitance: 100nF  (hidden comment: *)
Capacitor, Ceramic (MLCC), 100nF, 50V, Y5V, SMD 0603; Manufacturer: YAGEO; Manufacturer Part Number: CC0603ZRY5V9BB104; Temperature Rating: -20%~+80%
footprint CAP-0603 (0603 (1608M) Capacitor)
pins: 1, 2

## CC0603ZRY5V9BB223
designator C?  Capacitance: 22nF  (hidden comment: *)
Capacitor, Ceramic (MLCC), 22nF, 50V, Y5V, SMD 0603; Manufacturer: YAGEO; Manufacturer Part Number: CC0603ZRY5V9BB223; Temperature Rating: -20%~+80%
footprint CAP-0603 (0603 (1608M) Capacitor)
pins: 1, 2

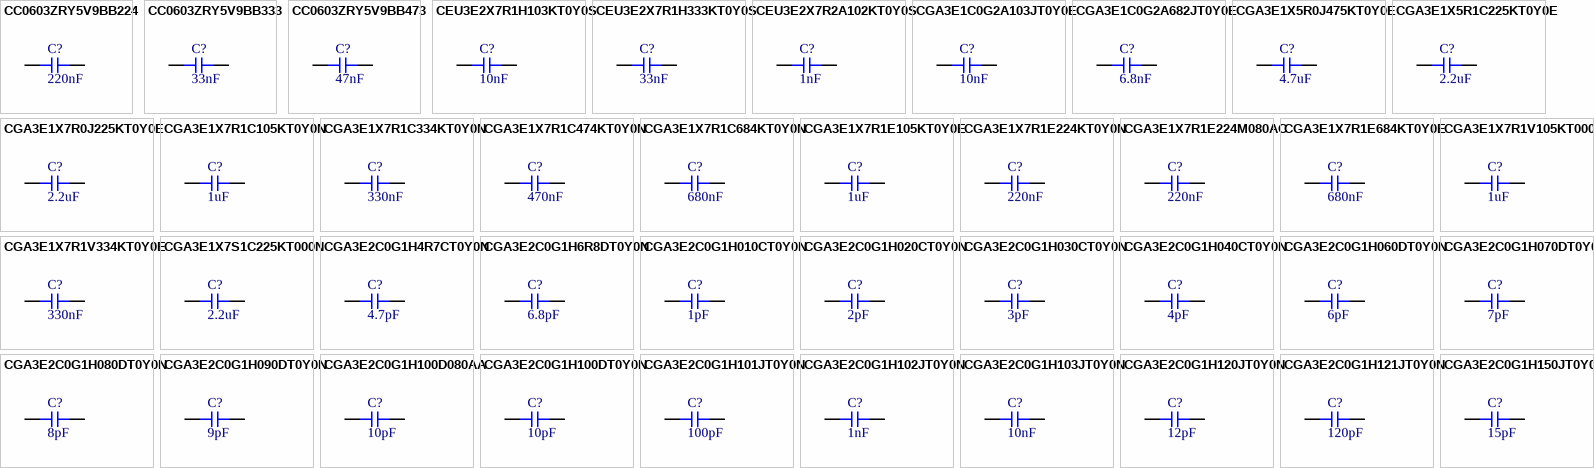
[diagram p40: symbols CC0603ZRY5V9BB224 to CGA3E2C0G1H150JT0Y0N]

## CC0603ZRY5V9BB224
designator C?  Capacitance: 220nF  (hidden comment: *)
Capacitor, Ceramic (MLCC), 220nF, 50V, Y5V, SMD 0603; Manufacturer: YAGEO; Manufacturer Part Number: CC0603ZRY5V9BB224; Temperature Rating: -20%~+80%
footprint CAP-0603 (0603 (1608M) Capacitor)
pins: 1, 2

## CC0603ZRY5V9BB333
designator C?  Capacitance: 33nF  (hidden comment: *)
Capacitor, Ceramic (MLCC), 33nF, 50V, Y5V, SMD 0603; Manufacturer: YAGEO; Manufacturer Part Number: CC0603ZRY5V9BB333; Temperature Rating: -20%~+80%
footprint CAP-0603 (0603 (1608M) Capacitor)
pins: 1, 2

## CC0603ZRY5V9BB473
designator C?  Capacitance: 47nF  (hidden comment: *)
Capacitor, Ceramic (MLCC), 47nF, 50V, Y5V, SMD 0603; Manufacturer: YAGEO; Manufacturer Part Number: CC0603ZRY5V9BB473; Temperature Rating: -20%~+80%
footprint CAP-0603 (0603 (1608M) Capacitor)
pins: 1, 2

## CEU3E2X7R1H103KT0Y0S
designator C?  Capacitance: 10nF  (hidden comment: *)
Capacitor, Ceramic (MLCC), 10nF, ±10%, 50V, X7R, ±10%, SMD 0603; Manufacturer: TDK; Manufacturer Part Number: CEU3E2X7R1H103KT0Y0S
footprint CAP-0603 (0603 (1608M) Capacitor)
pins: 1, 2

## CEU3E2X7R1H333KT0Y0S
designator C?  Capacitance: 33nF  (hidden comment: *)
Capacitor, Ceramic (MLCC), 33nF, ±10%, 50V, X7R, ±10%, SMD 0603; Manufacturer: TDK; Manufacturer Part Number: CEU3E2X7R1H333KT0Y0S
footprint CAP-0603 (0603 (1608M) Capacitor)
pins: 1, 2

## CEU3E2X7R2A102KT0Y0S
designator C?  Capacitance: 1nF  (hidden comment: *)
Capacitor, Ceramic (MLCC), 1nF, ±10%, 100V, X7R, ±10%, SMD 0603; Manufacturer: TDK; Manufacturer Part Number: CEU3E2X7R2A102KT0Y0S
footprint CAP-0603 (0603 (1608M) Capacitor)
pins: 1, 2

## CGA3E1C0G2A103JT0Y0E
designator C?  Capacitance: 10nF  (hidden comment: *)
Capacitor, Ceramic (MLCC), 10nF, ±5%, 100V, C0G, ±5%, SMD 0603; Manufacturer: TDK; Manufacturer Part Number: CGA3E1C0G2A103JT0Y0E
footprint CAP-0603 (0603 (1608M) Capacitor)
pins: 1, 2

## CGA3E1C0G2A682JT0Y0E
designator C?  Capacitance: 6.8nF  (hidden comment: *)
Capacitor, Ceramic (MLCC), 6.8nF, ±5%, 100V, C0G, ±5%, SMD 0603; Manufacturer: TDK; Manufacturer Part Number: CGA3E1C0G2A682JT0Y0E
footprint CAP-0603 (0603 (1608M) Capacitor)
pins: 1, 2

## CGA3E1X5R0J475KT0Y0E
designator C?  Capacitance: 4.7uF  (hidden comment: *)
Capacitor, Ceramic (MLCC), 4.7uF, ±10%, 6.3V, X5R, ±10%, SMD 0603; Manufacturer: TDK; Manufacturer Part Number: CGA3E1X5R0J475KT0Y0E
footprint CAP-0603 (0603 (1608M) Capacitor)
pins: 1, 2

## CGA3E1X5R1C225KT0Y0E
designator C?  Capacitance: 2.2uF  (hidden comment: *)
Capacitor, Ceramic (MLCC), 2.2uF, ±10%, 16V, X5R, ±10%, SMD 0603; Manufacturer: TDK; Manufacturer Part Number: CGA3E1X5R1C225KT0Y0E
footprint CAP-0603 (0603 (1608M) Capacitor)
pins: 1, 2

## CGA3E1X7R0J225KT0Y0E
designator C?  Capacitance: 2.2uF  (hidden comment: *)
Capacitor, Ceramic (MLCC), 2.2uF, ±10%, 6.3V, X7R, ±10%, SMD 0603; Manufacturer: TDK; Manufacturer Part Number: CGA3E1X7R0J225KT0Y0E
footprint CAP-0603 (0603 (1608M) Capacitor)
pins: 1, 2

## CGA3E1X7R1C105KT0Y0N
designator C?  Capacitance: 1uF  (hidden comment: *)
Capacitor, Ceramic (MLCC), 1uF, ±10%, 16V, X7R, ±10%, SMD 0603; Manufacturer: TDK; Manufacturer Part Number: CGA3E1X7R1C105KT0Y0N
footprint CAP-0603 (0603 (1608M) Capacitor)
pins: 1, 2

## CGA3E1X7R1C334KT0Y0N
designator C?  Capacitance: 330nF  (hidden comment: *)
Capacitor, Ceramic (MLCC), 330nF, ±10%, 16V, X7R, ±10%, SMD 0603; Manufacturer: TDK; Manufacturer Part Number: CGA3E1X7R1C334KT0Y0N
footprint CAP-0603 (0603 (1608M) Capacitor)
pins: 1, 2

## CGA3E1X7R1C474KT0Y0N
designator C?  Capacitance: 470nF  (hidden comment: *)
Capacitor, Ceramic (MLCC), 470nF, ±10%, 16V, X7R, ±10%, SMD 0603; Manufacturer: TDK; Manufacturer Part Number: CGA3E1X7R1C474KT0Y0N
footprint CAP-0603 (0603 (1608M) Capacitor)
pins: 1, 2

## CGA3E1X7R1C684KT0Y0N
designator C?  Capacitance: 680nF  (hidden comment: *)
Capacitor, Ceramic (MLCC), 680nF, ±10%, 16V, X7R, ±10%, SMD 0603; Manufacturer: TDK; Manufacturer Part Number: CGA3E1X7R1C684KT0Y0N
footprint CAP-0603 (0603 (1608M) Capacitor)
pins: 1, 2

## CGA3E1X7R1E105KT0Y0E
designator C?  Capacitance: 1uF  (hidden comment: *)
Capacitor, Ceramic (MLCC), 1uF, ±10%, 25V, X7R, ±10%, SMD 0603; Manufacturer: TDK; Manufacturer Part Number: CGA3E1X7R1E105KT0Y0E
footprint CAP-0603 (0603 (1608M) Capacitor)
pins: 1, 2

## CGA3E1X7R1E224KT0Y0N
designator C?  Capacitance: 220nF  (hidden comment: *)
Capacitor, Ceramic (MLCC), 220nF, ±10%, 25V, X7R, ±10%, SMD 0603; Manufacturer: TDK; Manufacturer Part Number: CGA3E1X7R1E224KT0Y0N
footprint CAP-0603 (0603 (1608M) Capacitor)
pins: 1, 2

## CGA3E1X7R1E224M080AC
designator C?  Capacitance: 220nF  (hidden comment: *)
Capacitor, Ceramic (MLCC), 220nF, ±20%, 25V, X7R, ±20%, SMD 0603; Manufacturer: TDK; Manufacturer Part Number: CGA3E1X7R1E224M080AC
footprint CAP-0603 (0603 (1608M) Capacitor)
pins: 1, 2

## CGA3E1X7R1E684KT0Y0E
designator C?  Capacitance: 680nF  (hidden comment: *)
Capacitor, Ceramic (MLCC), 680nF, ±10%, 25V, X7R, ±10%, SMD 0603; Manufacturer: TDK; Manufacturer Part Number: CGA3E1X7R1E684KT0Y0E
footprint CAP-0603 (0603 (1608M) Capacitor)
pins: 1, 2

## CGA3E1X7R1V105KT000N
designator C?  Capacitance: 1uF  (hidden comment: *)
Capacitor, Ceramic (MLCC), 1uF, ±10%, 35V, X7R, ±10%, SMD 0603; Manufacturer: TDK; Manufacturer Part Number: CGA3E1X7R1V105KT000N
footprint CAP-0603 (0603 (1608M) Capacitor)
pins: 1, 2

## CGA3E1X7R1V334KT0Y0E
designator C?  Capacitance: 330nF  (hidden comment: *)
Capacitor, Ceramic (MLCC), 330nF, ±10%, 35V, X7R, ±10%, SMD 0603; Manufacturer: TDK; Manufacturer Part Number: CGA3E1X7R1V334KT0Y0E
footprint CAP-0603 (0603 (1608M) Capacitor)
pins: 1, 2

## CGA3E1X7S1C225KT000N
designator C?  Capacitance: 2.2uF  (hidden comment: *)
Capacitor, Ceramic (MLCC), 2.2uF, ±10%, 16V, X7S, ±10%, SMD 0603; Manufacturer: TDK; Manufacturer Part Number: CGA3E1X7S1C225KT000N
footprint CAP-0603 (0603 (1608M) Capacitor)
pins: 1, 2

## CGA3E2C0G1H4R7CT0Y0N
designator C?  Capacitance: 4.7pF  (hidden comment: *)
Capacitor, Ceramic (MLCC), 4.7pF, ±0.25pF, 50V, C0G, ±0.25pF, SMD 0603; Manufacturer: TDK; Manufacturer Part Number: CGA3E2C0G1H4R7CT0Y0N
footprint CAP-0603 (0603 (1608M) Capacitor)
pins: 1, 2

## CGA3E2C0G1H6R8DT0Y0N
designator C?  Capacitance: 6.8pF  (hidden comment: *)
Capacitor, Ceramic (MLCC), 6.8pF, ±0.5pF, 50V, C0G, ±0.5pF, SMD 0603; Manufacturer: TDK; Manufacturer Part Number: CGA3E2C0G1H6R8DT0Y0N
footprint CAP-0603 (0603 (1608M) Capacitor)
pins: 1, 2

## CGA3E2C0G1H010CT0Y0N
designator C?  Capacitance: 1pF  (hidden comment: *)
Capacitor, Ceramic (MLCC), 1pF, ±0.25pF, 50V, C0G, ±0.25pF, SMD 0603; Manufacturer: TDK; Manufacturer Part Number: CGA3E2C0G1H010CT0Y0N
footprint CAP-0603 (0603 (1608M) Capacitor)
pins: 1, 2

## CGA3E2C0G1H020CT0Y0N
designator C?  Capacitance: 2pF  (hidden comment: *)
Capacitor, Ceramic (MLCC), 2pF, ±0.25pF, 50V, C0G, ±0.25pF, SMD 0603; Manufacturer: TDK; Manufacturer Part Number: CGA3E2C0G1H020CT0Y0N
footprint CAP-0603 (0603 (1608M) Capacitor)
pins: 1, 2

## CGA3E2C0G1H030CT0Y0N
designator C?  Capacitance: 3pF  (hidden comment: *)
Capacitor, Ceramic (MLCC), 3pF, ±0.25pF, 50V, C0G, ±0.25pF, SMD 0603; Manufacturer: TDK; Manufacturer Part Number: CGA3E2C0G1H030CT0Y0N
footprint CAP-0603 (0603 (1608M) Capacitor)
pins: 1, 2

## CGA3E2C0G1H040CT0Y0N
designator C?  Capacitance: 4pF  (hidden comment: *)
Capacitor, Ceramic (MLCC), 4pF, ±0.25pF, 50V, C0G, ±0.25pF, SMD 0603; Manufacturer: TDK; Manufacturer Part Number: CGA3E2C0G1H040CT0Y0N
footprint CAP-0603 (0603 (1608M) Capacitor)
pins: 1, 2

## CGA3E2C0G1H060DT0Y0N
designator C?  Capacitance: 6pF  (hidden comment: *)
Capacitor, Ceramic (MLCC), 6pF, ±0.5pF, 50V, C0G, ±0.5pF, SMD 0603; Manufacturer: TDK; Manufacturer Part Number: CGA3E2C0G1H060DT0Y0N
footprint CAP-0603 (0603 (1608M) Capacitor)
pins: 1, 2

## CGA3E2C0G1H070DT0Y0N
designator C?  Capacitance: 7pF  (hidden comment: *)
Capacitor, Ceramic (MLCC), 7pF, ±0.5pF, 50V, C0G, ±0.5pF, SMD 0603; Manufacturer: TDK; Manufacturer Part Number: CGA3E2C0G1H070DT0Y0N
footprint CAP-0603 (0603 (1608M) Capacitor)
pins: 1, 2

## CGA3E2C0G1H080DT0Y0N
designator C?  Capacitance: 8pF  (hidden comment: *)
Capacitor, Ceramic (MLCC), 8pF, ±0.5pF, 50V, C0G, ±0.5pF, SMD 0603; Manufacturer: TDK; Manufacturer Part Number: CGA3E2C0G1H080DT0Y0N
footprint CAP-0603 (0603 (1608M) Capacitor)
pins: 1, 2

## CGA3E2C0G1H090DT0Y0N
designator C?  Capacitance: 9pF  (hidden comment: *)
Capacitor, Ceramic (MLCC), 9pF, ±0.5pF, 50V, C0G, ±0.5pF, SMD 0603; Manufacturer: TDK; Manufacturer Part Number: CGA3E2C0G1H090DT0Y0N
footprint CAP-0603 (0603 (1608M) Capacitor)
pins: 1, 2

## CGA3E2C0G1H100D080AA
designator C?  Capacitance: 10pF  (hidden comment: *)
Capacitor, Ceramic (MLCC), 10pF, ±0.5pF, 50V, C0G, ±0.5pF, SMD 0603; Manufacturer: TDK; Manufacturer Part Number: CGA3E2C0G1H100D080AA
footprint CAP-0603 (0603 (1608M) Capacitor)
pins: 1, 2

## CGA3E2C0G1H100DT0Y0N
designator C?  Capacitance: 10pF  (hidden comment: *)
Capacitor, Ceramic (MLCC), 10pF, ±0.5pF, 50V, C0G, ±0.5pF, SMD 0603; Manufacturer: TDK; Manufacturer Part Number: CGA3E2C0G1H100DT0Y0N
footprint CAP-0603 (0603 (1608M) Capacitor)
pins: 1, 2

## CGA3E2C0G1H101JT0Y0N
designator C?  Capacitance: 100pF  (hidden comment: *)
Capacitor, Ceramic (MLCC), 100pF, ±5%, 50V, C0G, ±5%, SMD 0603; Manufacturer: TDK; Manufacturer Part Number: CGA3E2C0G1H101JT0Y0N
footprint CAP-0603 (0603 (1608M) Capacitor)
pins: 1, 2

## CGA3E2C0G1H102JT0Y0N
designator C?  Capacitance: 1nF  (hidden comment: *)
Capacitor, Ceramic (MLCC), 1nF, ±5%, 50V, C0G, ±5%, SMD 0603; Manufacturer: TDK; Manufacturer Part Number: CGA3E2C0G1H102JT0Y0N
footprint CAP-0603 (0603 (1608M) Capacitor)
pins: 1, 2

## CGA3E2C0G1H103JT0Y0N
designator C?  Capacitance: 10nF  (hidden comment: *)
Capacitor, Ceramic (MLCC), 10nF, ±5%, 50V, C0G, ±5%, SMD 0603; Manufacturer: TDK; Manufacturer Part Number: CGA3E2C0G1H103JT0Y0N
footprint CAP-0603 (0603 (1608M) Capacitor)
pins: 1, 2

## CGA3E2C0G1H120JT0Y0N
designator C?  Capacitance: 12pF  (hidden comment: *)
Capacitor, Ceramic (MLCC), 12pF, ±5%, 50V, C0G, ±5%, SMD 0603; Manufacturer: TDK; Manufacturer Part Number: CGA3E2C0G1H120JT0Y0N
footprint CAP-0603 (0603 (1608M) Capacitor)
pins: 1, 2

## CGA3E2C0G1H121JT0Y0N
designator C?  Capacitance: 120pF  (hidden comment: *)
Capacitor, Ceramic (MLCC), 120pF, ±5%, 50V, C0G, ±5%, SMD 0603; Manufacturer: TDK; Manufacturer Part Number: CGA3E2C0G1H121JT0Y0N
footprint CAP-0603 (0603 (1608M) Capacitor)
pins: 1, 2

## CGA3E2C0G1H150JT0Y0N
designator C?  Capacitance: 15pF  (hidden comment: *)
Capacitor, Ceramic (MLCC), 15pF, ±5%, 50V, C0G, ±5%, SMD 0603; Manufacturer: TDK; Manufacturer Part Number: CGA3E2C0G1H150JT0Y0N
footprint CAP-0603 (0603 (1608M) Capacitor)
pins: 1, 2

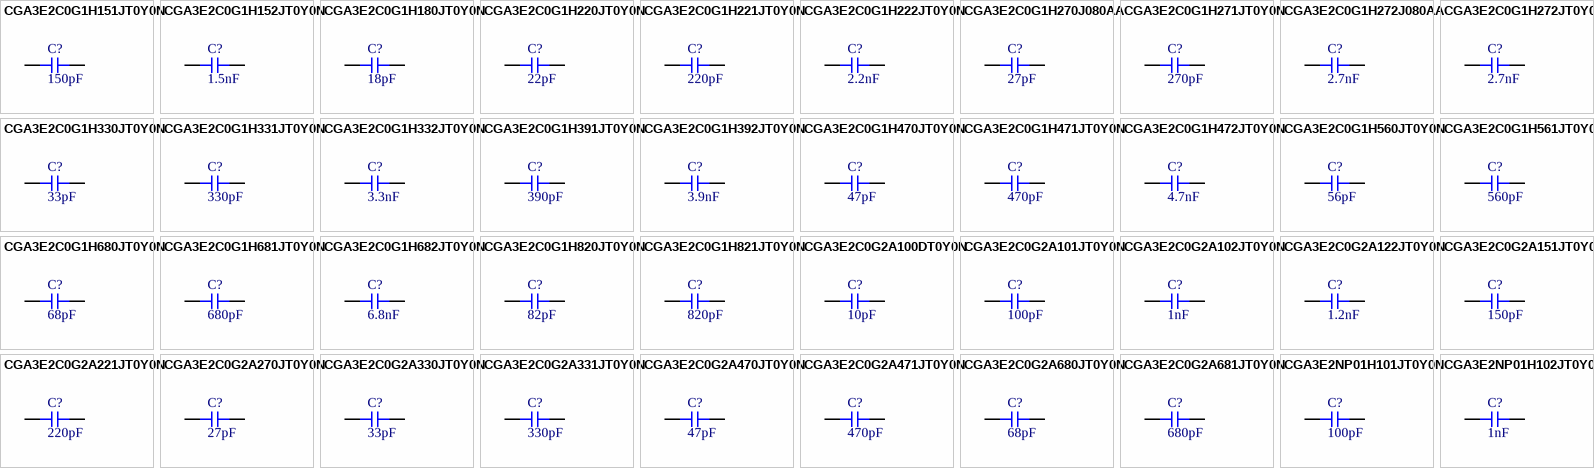
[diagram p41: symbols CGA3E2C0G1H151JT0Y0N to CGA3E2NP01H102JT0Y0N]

## CGA3E2C0G1H151JT0Y0N
designator C?  Capacitance: 150pF  (hidden comment: *)
Capacitor, Ceramic (MLCC), 150pF, ±5%, 50V, C0G, ±5%, SMD 0603; Manufacturer: TDK; Manufacturer Part Number: CGA3E2C0G1H151JT0Y0N
footprint CAP-0603 (0603 (1608M) Capacitor)
pins: 1, 2

## CGA3E2C0G1H152JT0Y0N
designator C?  Capacitance: 1.5nF  (hidden comment: *)
Capacitor, Ceramic (MLCC), 1.5nF, ±5%, 50V, C0G, ±5%, SMD 0603; Manufacturer: TDK; Manufacturer Part Number: CGA3E2C0G1H152JT0Y0N
footprint CAP-0603 (0603 (1608M) Capacitor)
pins: 1, 2

## CGA3E2C0G1H180JT0Y0N
designator C?  Capacitance: 18pF  (hidden comment: *)
Capacitor, Ceramic (MLCC), 18pF, ±5%, 50V, C0G, ±5%, SMD 0603; Manufacturer: TDK; Manufacturer Part Number: CGA3E2C0G1H180JT0Y0N
footprint CAP-0603 (0603 (1608M) Capacitor)
pins: 1, 2

## CGA3E2C0G1H220JT0Y0N
designator C?  Capacitance: 22pF  (hidden comment: *)
Capacitor, Ceramic (MLCC), 22pF, ±5%, 50V, C0G, ±5%, SMD 0603; Manufacturer: TDK; Manufacturer Part Number: CGA3E2C0G1H220JT0Y0N
footprint CAP-0603 (0603 (1608M) Capacitor)
pins: 1, 2

## CGA3E2C0G1H221JT0Y0N
designator C?  Capacitance: 220pF  (hidden comment: *)
Capacitor, Ceramic (MLCC), 220pF, ±5%, 50V, C0G, ±5%, SMD 0603; Manufacturer: TDK; Manufacturer Part Number: CGA3E2C0G1H221JT0Y0N
footprint CAP-0603 (0603 (1608M) Capacitor)
pins: 1, 2

## CGA3E2C0G1H222JT0Y0N
designator C?  Capacitance: 2.2nF  (hidden comment: *)
Capacitor, Ceramic (MLCC), 2.2nF, ±5%, 50V, C0G, ±5%, SMD 0603; Manufacturer: TDK; Manufacturer Part Number: CGA3E2C0G1H222JT0Y0N
footprint CAP-0603 (0603 (1608M) Capacitor)
pins: 1, 2

## CGA3E2C0G1H270J080AA
designator C?  Capacitance: 27pF  (hidden comment: *)
Capacitor, Ceramic (MLCC), 27pF, ±5%, 50V, C0G, ±5%, SMD 0603; Manufacturer: TDK; Manufacturer Part Number: CGA3E2C0G1H270J080AA
footprint CAP-0603 (0603 (1608M) Capacitor)
pins: 1, 2

## CGA3E2C0G1H271JT0Y0N
designator C?  Capacitance: 270pF  (hidden comment: *)
Capacitor, Ceramic (MLCC), 270pF, ±5%, 50V, C0G, ±5%, SMD 0603; Manufacturer: TDK; Manufacturer Part Number: CGA3E2C0G1H271JT0Y0N
footprint CAP-0603 (0603 (1608M) Capacitor)
pins: 1, 2

## CGA3E2C0G1H272J080AA
designator C?  Capacitance: 2.7nF  (hidden comment: *)
Capacitor, Ceramic (MLCC), 2.7nF, ±5%, 50V, C0G, ±5%, SMD 0603; Manufacturer: TDK; Manufacturer Part Number: CGA3E2C0G1H272J080AA
footprint CAP-0603 (0603 (1608M) Capacitor)
pins: 1, 2

## CGA3E2C0G1H272JT0Y0N
designator C?  Capacitance: 2.7nF  (hidden comment: *)
Capacitor, Ceramic (MLCC), 2.7nF, ±5%, 50V, C0G, ±5%, SMD 0603; Manufacturer: TDK; Manufacturer Part Number: CGA3E2C0G1H272JT0Y0N
footprint CAP-0603 (0603 (1608M) Capacitor)
pins: 1, 2

## CGA3E2C0G1H330JT0Y0N
designator C?  Capacitance: 33pF  (hidden comment: *)
Capacitor, Ceramic (MLCC), 33pF, ±5%, 50V, C0G, ±5%, SMD 0603; Manufacturer: TDK; Manufacturer Part Number: CGA3E2C0G1H330JT0Y0N
footprint CAP-0603 (0603 (1608M) Capacitor)
pins: 1, 2

## CGA3E2C0G1H331JT0Y0N
designator C?  Capacitance: 330pF  (hidden comment: *)
Capacitor, Ceramic (MLCC), 330pF, ±5%, 50V, C0G, ±5%, SMD 0603; Manufacturer: TDK; Manufacturer Part Number: CGA3E2C0G1H331JT0Y0N
footprint CAP-0603 (0603 (1608M) Capacitor)
pins: 1, 2

## CGA3E2C0G1H332JT0Y0N
designator C?  Capacitance: 3.3nF  (hidden comment: *)
Capacitor, Ceramic (MLCC), 3.3nF, ±5%, 50V, C0G, ±5%, SMD 0603; Manufacturer: TDK; Manufacturer Part Number: CGA3E2C0G1H332JT0Y0N
footprint CAP-0603 (0603 (1608M) Capacitor)
pins: 1, 2

## CGA3E2C0G1H391JT0Y0N
designator C?  Capacitance: 390pF  (hidden comment: *)
Capacitor, Ceramic (MLCC), 390pF, ±5%, 50V, C0G, ±5%, SMD 0603; Manufacturer: TDK; Manufacturer Part Number: CGA3E2C0G1H391JT0Y0N
footprint CAP-0603 (0603 (1608M) Capacitor)
pins: 1, 2

## CGA3E2C0G1H392JT0Y0N
designator C?  Capacitance: 3.9nF  (hidden comment: *)
Capacitor, Ceramic (MLCC), 3.9nF, ±5%, 50V, C0G, ±5%, SMD 0603; Manufacturer: TDK; Manufacturer Part Number: CGA3E2C0G1H392JT0Y0N
footprint CAP-0603 (0603 (1608M) Capacitor)
pins: 1, 2

## CGA3E2C0G1H470JT0Y0N
designator C?  Capacitance: 47pF  (hidden comment: *)
Capacitor, Ceramic (MLCC), 47pF, ±5%, 50V, C0G, ±5%, SMD 0603; Manufacturer: TDK; Manufacturer Part Number: CGA3E2C0G1H470JT0Y0N
footprint CAP-0603 (0603 (1608M) Capacitor)
pins: 1, 2

## CGA3E2C0G1H471JT0Y0N
designator C?  Capacitance: 470pF  (hidden comment: *)
Capacitor, Ceramic (MLCC), 470pF, ±5%, 50V, C0G, ±5%, SMD 0603; Manufacturer: TDK; Manufacturer Part Number: CGA3E2C0G1H471JT0Y0N
footprint CAP-0603 (0603 (1608M) Capacitor)
pins: 1, 2

## CGA3E2C0G1H472JT0Y0N
designator C?  Capacitance: 4.7nF  (hidden comment: *)
Capacitor, Ceramic (MLCC), 4.7nF, ±5%, 50V, C0G, ±5%, SMD 0603; Manufacturer: TDK; Manufacturer Part Number: CGA3E2C0G1H472JT0Y0N
footprint CAP-0603 (0603 (1608M) Capacitor)
pins: 1, 2

## CGA3E2C0G1H560JT0Y0N
designator C?  Capacitance: 56pF  (hidden comment: *)
Capacitor, Ceramic (MLCC), 56pF, ±5%, 50V, C0G, ±5%, SMD 0603; Manufacturer: TDK; Manufacturer Part Number: CGA3E2C0G1H560JT0Y0N
footprint CAP-0603 (0603 (1608M) Capacitor)
pins: 1, 2

## CGA3E2C0G1H561JT0Y0N
designator C?  Capacitance: 560pF  (hidden comment: *)
Capacitor, Ceramic (MLCC), 560pF, ±5%, 50V, C0G, ±5%, SMD 0603; Manufacturer: TDK; Manufacturer Part Number: CGA3E2C0G1H561JT0Y0N
footprint CAP-0603 (0603 (1608M) Capacitor)
pins: 1, 2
